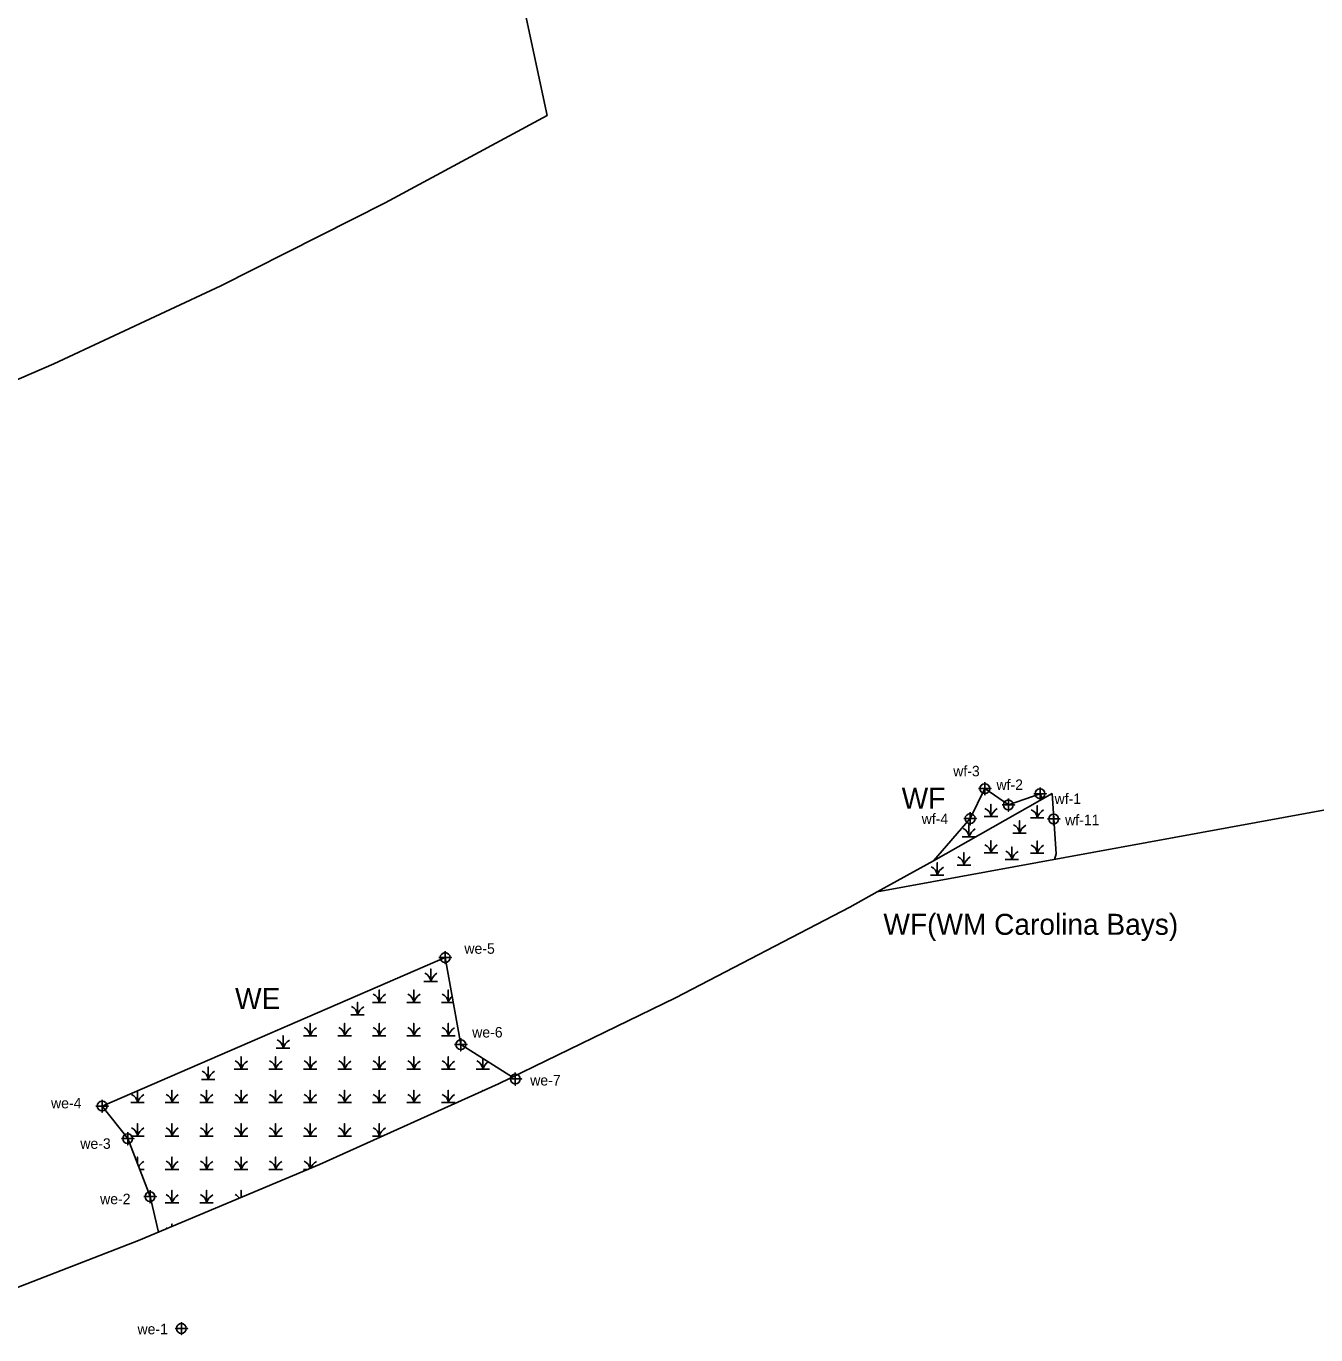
# Model space of a CAD drawing. Extents: x 2174810 to 2196950, y 76168 to 88270.
# Drawn here: x 2175379 to 2175994, y 76289 to 76913 of the extents above; entities that cross this region are included whole.
import ezdxf

# ---------------------------------------------------------------- set-up
doc = ezdxf.new("R2010")
doc.units = 0
for name, color, linetype in [('Default', 7, 'Continuous'), ('Exist Environmental Wetland Boundary', 7, 'Continuous'), ('Exist Environmental Wetland Boundary Cogo Number', 7, 'Continuous'), ('Exist Environmental Wetland Boundary Cogo Point CELL', 7, 'Continuous'), ('Exist Environmental Wetland Boundary Text', 7, 'Continuous'), ('Exist Hydro Swamp or Marsh', 7, 'Continuous')]:
    doc.layers.add(name, color=color, linetype=linetype)

msp = doc.modelspace()

# ---------------------------------------------------------------- linework, layer by layer
at = {"layer": 'Default'}
for points in [[(2175311.89, 76716.94), (2175392.42, 76751.76), (2175471.91, 76788.91), (2175550.27, 76828.38), (2175627.45, 76870.11), (2175551.73, 77223.26)], [(2176080.61, 76554.38), (2175784.69, 76500.24), (2175771.53, 76492.93), (2175688.49, 76449.77), (2175604.3, 76408.9), (2175519.02, 76370.37), (2175432.71, 76334.2), (2175345.43, 76300.42)]]:
    msp.add_lwpolyline(points, dxfattribs=at)
at = {"layer": 'Exist Environmental Wetland Boundary'}
for p, q in [((2175811.46, 76515.11), (2175868.02, 76547.06)), ((2175868.02, 76547.06), (2175869.85, 76518.43)), ((2175784.69, 76500.24), (2175811.46, 76515.11)), ((2175869.85, 76518.43), (2175869.09, 76515.68)), ((2175869.09, 76515.68), (2175869.09, 76515.68))]:
    msp.add_line(p, q, dxfattribs=at)
for points in [[(2175811.46, 76515.11), (2175828.93, 76535.2), (2175835.91, 76549.46), (2175847.11, 76541.72), (2175862.19, 76546.99), (2175863.57, 76544.43)], [(2175442.26, 76338.2), (2175438.24, 76355.14), (2175427.59, 76382.78), (2175415.44, 76398.28), (2175578.82, 76469.01), (2175586.29, 76427.53), (2175610.84, 76412.07)]]:
    msp.add_lwpolyline(points, dxfattribs=at)
at = {"layer": 'Exist Environmental Wetland Boundary Cogo Point CELL'}
for points in [[(2175835.91, 76552.46), (2175835.91, 76546.46), (2175835.91, 76549.46), (2175838.91, 76549.46), (2175832.91, 76549.46)], [(2175862.19, 76549.99), (2175862.19, 76543.99), (2175862.19, 76546.99), (2175865.19, 76546.99), (2175859.19, 76546.99)], [(2175847.11, 76544.72), (2175847.11, 76538.72), (2175847.11, 76541.72), (2175850.11, 76541.72), (2175844.11, 76541.72)], [(2175828.93, 76538.2), (2175828.93, 76532.2), (2175828.93, 76535.2), (2175831.93, 76535.2), (2175825.93, 76535.2)], [(2175868.69, 76538), (2175868.69, 76532), (2175868.69, 76535), (2175871.69, 76535), (2175865.69, 76535)], [(2175578.82, 76472.01), (2175578.82, 76466.01), (2175578.82, 76469.01), (2175581.82, 76469.01), (2175575.82, 76469.01)], [(2175586.29, 76430.53), (2175586.29, 76424.53), (2175586.29, 76427.53), (2175589.29, 76427.53), (2175583.29, 76427.53)], [(2175612.22, 76414.2), (2175612.22, 76408.2), (2175612.22, 76411.2), (2175615.22, 76411.2), (2175609.22, 76411.2)], [(2175415.44, 76401.28), (2175415.44, 76395.28), (2175415.44, 76398.28), (2175418.44, 76398.28), (2175412.44, 76398.28)], [(2175427.59, 76385.78), (2175427.59, 76379.78), (2175427.59, 76382.78), (2175430.59, 76382.78), (2175424.59, 76382.78)], [(2175438.24, 76358.14), (2175438.24, 76352.14), (2175438.24, 76355.14), (2175441.24, 76355.14), (2175435.24, 76355.14)], [(2175453.17, 76295.32), (2175453.17, 76289.32), (2175453.17, 76292.32), (2175456.17, 76292.32), (2175450.17, 76292.32)]]:
    msp.add_lwpolyline(points, dxfattribs=at)
for centre in [(2175835.91, 76549.46), (2175862.19, 76546.99), (2175847.11, 76541.72), (2175828.93, 76535.2), (2175868.69, 76535), (2175578.82, 76469.01), (2175586.29, 76427.53), (2175612.22, 76411.2), (2175415.44, 76398.28), (2175427.59, 76382.78), (2175438.24, 76355.14), (2175453.17, 76292.32)]:
    msp.add_circle(centre, 2.34, dxfattribs=at)
at = {"layer": 'Exist Hydro Swamp or Marsh'}
for p, q in [((2175433.25, 76368.07), (2175435.47, 76368.07)), ((2175511.28, 76368.07), (2175513.54, 76368.07))]:
    msp.add_line(p, q, dxfattribs=at)
for points in [[(2175835.58, 76536.13), (2175838.81, 76536.13), (2175838.81, 76542.05), (2175838.81, 76536.13), (2175842.03, 76536.13)], [(2175857.62, 76535.49), (2175860.84, 76535.49), (2175860.84, 76541.41), (2175860.84, 76535.49), (2175864.07, 76535.49)], [(2175825.13, 76526.5), (2175828.35, 76526.5), (2175828.35, 76532.42), (2175828.35, 76526.5), (2175831.58, 76526.5)], [(2175849.21, 76528.23), (2175852.44, 76528.23), (2175852.44, 76534.15), (2175852.44, 76528.23), (2175855.66, 76528.23)], [(2175835.58, 76518.8), (2175838.81, 76518.8), (2175838.81, 76524.72), (2175838.81, 76518.8), (2175842.03, 76518.8)], [(2175845.52, 76515.74), (2175848.74, 76515.74), (2175848.74, 76521.66), (2175848.74, 76515.74), (2175851.97, 76515.74)], [(2175857.62, 76518.67), (2175860.84, 76518.67), (2175860.84, 76524.59), (2175860.84, 76518.67), (2175864.07, 76518.67)], [(2175809.98, 76508.22), (2175813.2, 76508.22), (2175813.2, 76514.14), (2175813.2, 76508.22), (2175816.43, 76508.22)], [(2175822.72, 76513.06), (2175825.94, 76513.06), (2175825.94, 76518.98), (2175825.94, 76513.06), (2175829.17, 76513.06)], [(2175568.71, 76457.67), (2175571.93, 76457.67), (2175571.93, 76463.58), (2175571.93, 76457.67), (2175575.16, 76457.67)], [(2175544.18, 76447.66), (2175547.4, 76447.66), (2175547.4, 76453.58), (2175547.4, 76447.66), (2175550.63, 76447.66)], [(2175560.63, 76447.66), (2175563.86, 76447.66), (2175563.86, 76453.58), (2175563.86, 76447.66), (2175567.08, 76447.66)], [(2175577.08, 76447.66), (2175580.31, 76447.66), (2175580.31, 76453.58), (2175580.31, 76447.66), (2175582.66, 76447.66)], [(2175533.85, 76441.75), (2175537.08, 76441.75), (2175537.08, 76447.67), (2175537.08, 76441.75), (2175540.31, 76441.75)], [(2175511.28, 76431.75), (2175514.5, 76431.75), (2175514.5, 76437.66), (2175514.5, 76431.75), (2175517.73, 76431.75)], [(2175527.73, 76431.75), (2175530.95, 76431.75), (2175530.95, 76437.66), (2175530.95, 76431.75), (2175534.18, 76431.75)], [(2175544.18, 76431.75), (2175547.4, 76431.75), (2175547.4, 76437.66), (2175547.4, 76431.75), (2175550.63, 76431.75)], [(2175560.63, 76431.75), (2175563.86, 76431.75), (2175563.86, 76437.66), (2175563.86, 76431.75), (2175567.08, 76431.75)], [(2175577.08, 76431.75), (2175580.31, 76431.75), (2175580.31, 76437.66), (2175580.31, 76431.75), (2175583.53, 76431.75)], [(2175498.4, 76425.83), (2175501.62, 76425.83), (2175501.62, 76431.75), (2175501.62, 76425.83), (2175504.85, 76425.83)], [(2175478.37, 76415.83), (2175481.6, 76415.83), (2175481.6, 76421.75), (2175481.6, 76415.83), (2175484.83, 76415.83)], [(2175494.83, 76415.83), (2175498.05, 76415.83), (2175498.05, 76421.75), (2175498.05, 76415.83), (2175501.28, 76415.83)], [(2175511.28, 76415.83), (2175514.5, 76415.83), (2175514.5, 76421.75), (2175514.5, 76415.83), (2175517.73, 76415.83)], [(2175527.73, 76415.83), (2175530.95, 76415.83), (2175530.95, 76421.75), (2175530.95, 76415.83), (2175534.18, 76415.83)], [(2175544.18, 76415.83), (2175547.4, 76415.83), (2175547.4, 76421.75), (2175547.4, 76415.83), (2175550.63, 76415.83)], [(2175560.63, 76415.83), (2175563.86, 76415.83), (2175563.86, 76421.75), (2175563.86, 76415.83), (2175567.08, 76415.83)], [(2175577.08, 76415.83), (2175580.31, 76415.83), (2175580.31, 76421.75), (2175580.31, 76415.83), (2175583.53, 76415.83)], [(2175593.53, 76415.83), (2175596.76, 76415.83), (2175596.76, 76420.94)], [(2175596.76, 76420.94), (2175596.76, 76415.83), (2175599.98, 76415.83)], [(2175462.71, 76410.98), (2175465.94, 76410.98), (2175465.94, 76416.9), (2175465.94, 76410.98), (2175469.16, 76410.98)], [(2175429.02, 76399.91), (2175432.25, 76399.91), (2175432.25, 76405.55)], [(2175432.25, 76405.55), (2175432.25, 76399.91), (2175435.47, 76399.91)], [(2175445.47, 76399.91), (2175448.7, 76399.91), (2175448.7, 76405.83), (2175448.7, 76399.91), (2175451.92, 76399.91)], [(2175461.92, 76399.91), (2175465.15, 76399.91), (2175465.15, 76405.83), (2175465.15, 76399.91), (2175468.37, 76399.91)], [(2175478.37, 76399.91), (2175481.6, 76399.91), (2175481.6, 76405.83), (2175481.6, 76399.91), (2175484.83, 76399.91)], [(2175494.83, 76399.91), (2175498.05, 76399.91), (2175498.05, 76405.83), (2175498.05, 76399.91), (2175501.28, 76399.91)], [(2175511.28, 76399.91), (2175514.5, 76399.91), (2175514.5, 76405.83), (2175514.5, 76399.91), (2175517.73, 76399.91)], [(2175527.73, 76399.91), (2175530.95, 76399.91), (2175530.95, 76405.83), (2175530.95, 76399.91), (2175534.18, 76399.91)], [(2175544.18, 76399.91), (2175547.4, 76399.91), (2175547.4, 76405.83), (2175547.4, 76399.91), (2175550.63, 76399.91)], [(2175560.63, 76399.91), (2175563.86, 76399.91), (2175563.86, 76405.83), (2175563.86, 76399.91), (2175567.08, 76399.91)], [(2175577.08, 76399.91), (2175580.31, 76399.91), (2175580.31, 76405.83), (2175580.31, 76399.91), (2175583.53, 76399.91)], [(2175596.76, 76405.49), (2175596.76, 76405.83), (2175596.76, 76405.49)], [(2175429.02, 76383.99), (2175432.25, 76383.99), (2175432.25, 76389.91), (2175432.25, 76383.99), (2175435.47, 76383.99)], [(2175445.47, 76383.99), (2175448.7, 76383.99), (2175448.7, 76389.91), (2175448.7, 76383.99), (2175451.92, 76383.99)], [(2175461.92, 76383.99), (2175465.15, 76383.99), (2175465.15, 76389.91), (2175465.15, 76383.99), (2175468.37, 76383.99)], [(2175478.37, 76383.99), (2175481.6, 76383.99), (2175481.6, 76389.91), (2175481.6, 76383.99), (2175484.83, 76383.99)], [(2175494.83, 76383.99), (2175498.05, 76383.99), (2175498.05, 76389.91), (2175498.05, 76383.99), (2175501.28, 76383.99)], [(2175511.28, 76383.99), (2175514.5, 76383.99), (2175514.5, 76389.91), (2175514.5, 76383.99), (2175517.73, 76383.99)], [(2175527.73, 76383.99), (2175530.95, 76383.99), (2175530.95, 76389.91), (2175530.95, 76383.99), (2175534.18, 76383.99)], [(2175544.18, 76383.99), (2175547.4, 76383.99), (2175547.4, 76389.91), (2175547.4, 76383.99), (2175549.17, 76383.99)], [(2175432.25, 76370.69), (2175432.25, 76373.99), (2175432.25, 76370.69)], [(2175445.47, 76368.07), (2175448.7, 76368.07), (2175448.7, 76373.99), (2175448.7, 76368.07), (2175451.92, 76368.07)], [(2175461.92, 76368.07), (2175465.15, 76368.07), (2175465.15, 76373.99), (2175465.15, 76368.07), (2175468.37, 76368.07)], [(2175478.37, 76368.07), (2175481.6, 76368.07), (2175481.6, 76373.99), (2175481.6, 76368.07), (2175484.83, 76368.07)], [(2175494.83, 76368.07), (2175498.05, 76368.07), (2175498.05, 76373.99), (2175498.05, 76368.07), (2175501.28, 76368.07)], [(2175514.5, 76368.48), (2175514.5, 76373.99), (2175514.5, 76368.48)], [(2175445.47, 76352.16), (2175448.7, 76352.16), (2175448.7, 76358.07), (2175448.7, 76352.16), (2175451.92, 76352.16)], [(2175461.92, 76352.16), (2175465.15, 76352.16), (2175465.15, 76358.07), (2175465.15, 76352.16), (2175468.37, 76352.16)], [(2175481.6, 76354.69), (2175481.6, 76358.07), (2175481.6, 76354.69)], [(2175448.7, 76340.9), (2175448.7, 76342.16), (2175448.7, 76340.9)]]:
    msp.add_lwpolyline(points, dxfattribs=at)
for centre, radius, start, end in [((2175834.21, 76535.8), 4.61, 4.14034, 67.53497), ((2175845.65, 76533.86), 7.21, 122.12745, 161.62219), ((2175856.24, 76535.16), 4.61, 4.14034, 67.53497), ((2175867.69, 76533.22), 7.21, 122.12745, 161.62219), ((2175823.75, 76526.17), 4.61, 4.14034, 67.53497), ((2175835.19, 76524.23), 7.21, 122.12745, 161.62219), ((2175847.84, 76527.89), 4.61, 4.14034, 67.53497), ((2175859.28, 76525.96), 7.21, 122.12745, 161.62219), ((2175834.21, 76518.46), 4.61, 4.14034, 67.53497), ((2175845.65, 76516.52), 7.21, 122.12745, 161.62219), ((2175856.24, 76518.34), 4.61, 4.14034, 67.53497), ((2175867.69, 76516.4), 7.21, 122.12745, 161.62219), ((2175821.34, 76512.73), 4.61, 4.14034, 67.53497), ((2175832.78, 76510.79), 7.21, 122.12745, 161.62219), ((2175844.14, 76515.41), 4.61, 4.14034, 67.53497), ((2175855.58, 76513.47), 7.21, 122.12745, 161.62219), ((2175808.6, 76507.89), 4.61, 4.14034, 67.53497), ((2175820.05, 76505.95), 7.21, 122.12745, 161.62219), ((2175567.33, 76457.33), 4.61, 4.14034, 67.53497), ((2175578.77, 76455.39), 7.21, 122.12745, 161.62219), ((2175542.8, 76447.33), 4.61, 4.14034, 67.53497), ((2175554.25, 76445.39), 7.21, 122.12745, 161.62219), ((2175559.26, 76447.33), 4.61, 4.14034, 67.53497), ((2175570.7, 76445.39), 7.21, 122.12745, 161.62219), ((2175575.71, 76447.33), 4.61, 4.14034, 67.53497), ((2175532.48, 76441.42), 4.61, 4.14034, 67.53497), ((2175543.92, 76439.48), 7.21, 122.12745, 161.62219), ((2175587.15, 76445.39), 7.21, 133.9993, 161.62219), ((2175509.9, 76431.41), 4.61, 4.14034, 67.53497), ((2175521.34, 76429.47), 7.21, 122.12745, 161.62219), ((2175526.35, 76431.41), 4.61, 4.14034, 67.53497), ((2175537.79, 76429.47), 7.21, 122.12745, 161.62219), ((2175542.8, 76431.41), 4.61, 4.14034, 67.53497), ((2175554.25, 76429.47), 7.21, 122.12745, 161.62219), ((2175559.26, 76431.41), 4.61, 4.14034, 67.53497), ((2175570.7, 76429.47), 7.21, 122.12745, 161.62219), ((2175575.71, 76431.41), 4.61, 4.14034, 67.53497), ((2175587.15, 76429.47), 7.21, 122.12745, 161.62219), ((2175497.02, 76425.5), 4.61, 4.14034, 67.53497), ((2175508.46, 76423.56), 7.21, 122.12745, 161.62219), ((2175461.34, 76410.65), 4.61, 4.14034, 67.53497), ((2175472.78, 76408.71), 7.21, 122.12745, 161.62219), ((2175477, 76415.49), 4.61, 4.14034, 67.53497), ((2175488.44, 76413.56), 7.21, 122.12745, 161.62219), ((2175493.45, 76415.49), 4.61, 4.14034, 67.53497), ((2175504.89, 76413.56), 7.21, 122.12745, 161.62219), ((2175509.9, 76415.49), 4.61, 4.14034, 67.53497), ((2175521.34, 76413.56), 7.21, 122.12745, 161.62219), ((2175526.35, 76415.49), 4.61, 4.14034, 67.53497), ((2175537.79, 76413.56), 7.21, 122.12745, 161.62219), ((2175542.8, 76415.49), 4.61, 4.14034, 67.53497), ((2175554.25, 76413.56), 7.21, 122.12745, 161.62219), ((2175559.26, 76415.49), 4.61, 4.14034, 67.53497), ((2175570.7, 76413.56), 7.21, 122.12745, 161.62219), ((2175575.71, 76415.49), 4.61, 4.14034, 67.53497), ((2175587.15, 76413.56), 7.21, 122.12745, 161.62219), ((2175592.16, 76415.49), 4.61, 4.14034, 67.53497), ((2175603.6, 76413.56), 7.21, 126.64867, 161.62219), ((2175427.65, 76399.58), 4.61, 4.14034, 67.53497), ((2175439.09, 76397.64), 7.21, 122.12745, 161.62219), ((2175444.1, 76399.58), 4.61, 4.14034, 67.53497), ((2175455.54, 76397.64), 7.21, 122.12745, 161.62219), ((2175460.55, 76399.58), 4.61, 4.14034, 67.53497), ((2175471.99, 76397.64), 7.21, 122.12745, 161.62219), ((2175477, 76399.58), 4.61, 4.14034, 67.53497), ((2175488.44, 76397.64), 7.21, 122.12745, 161.62219), ((2175493.45, 76399.58), 4.61, 4.14034, 67.53497), ((2175504.89, 76397.64), 7.21, 122.12745, 161.62219), ((2175509.9, 76399.58), 4.61, 4.14034, 67.53497), ((2175521.34, 76397.64), 7.21, 122.12745, 161.62219), ((2175526.35, 76399.58), 4.61, 4.14034, 67.53497), ((2175537.79, 76397.64), 7.21, 122.12745, 161.62219), ((2175542.8, 76399.58), 4.61, 4.14034, 67.53497), ((2175554.25, 76397.64), 7.21, 122.12745, 161.62219), ((2175559.26, 76399.58), 4.61, 4.14034, 67.53497), ((2175570.7, 76397.64), 7.21, 122.12745, 161.62219), ((2175575.71, 76399.58), 4.61, 4.14034, 67.53497), ((2175587.15, 76397.64), 7.21, 122.12745, 161.62219), ((2175427.65, 76383.66), 4.61, 4.14034, 67.53497), ((2175439.09, 76381.72), 7.21, 122.12745, 161.62219), ((2175444.1, 76383.66), 4.61, 4.14034, 67.53497), ((2175455.54, 76381.72), 7.21, 122.12745, 161.62219), ((2175460.55, 76383.66), 4.61, 4.14034, 67.53497), ((2175471.99, 76381.72), 7.21, 122.12745, 161.62219), ((2175477, 76383.66), 4.61, 4.14034, 67.53497), ((2175488.44, 76381.72), 7.21, 122.12745, 161.62219), ((2175493.45, 76383.66), 4.61, 4.14034, 67.53497), ((2175504.89, 76381.72), 7.21, 122.12745, 161.62219), ((2175509.9, 76383.66), 4.61, 4.14034, 67.53497), ((2175521.34, 76381.72), 7.21, 122.12745, 161.62219), ((2175526.35, 76383.66), 4.61, 4.14034, 67.53497), ((2175537.79, 76381.72), 7.21, 122.12745, 161.62219), ((2175542.8, 76383.66), 4.61, 4.14034, 67.53497), ((2175554.25, 76381.72), 7.21, 122.12745, 161.62219), ((2175439.09, 76365.8), 7.21, 122.12745, 151.00607), ((2175444.1, 76367.74), 4.61, 4.14034, 67.53497), ((2175455.54, 76365.8), 7.21, 122.12745, 161.62219), ((2175460.55, 76367.74), 4.61, 4.14034, 67.53497), ((2175471.99, 76365.8), 7.21, 122.12745, 161.62219), ((2175477, 76367.74), 4.61, 4.14034, 67.53497), ((2175488.44, 76365.8), 7.21, 122.12745, 161.62219), ((2175493.45, 76367.74), 4.61, 4.14034, 67.53497), ((2175504.89, 76365.8), 7.21, 122.12745, 161.62219), ((2175509.9, 76367.74), 4.61, 8.95005, 67.53497), ((2175521.34, 76365.8), 7.21, 122.12745, 157.57268), ((2175444.1, 76351.82), 4.61, 4.14034, 67.53497), ((2175455.54, 76349.88), 7.21, 122.12745, 161.62219), ((2175460.55, 76351.82), 4.61, 4.14034, 67.53497), ((2175471.99, 76349.88), 7.21, 122.12745, 161.62219), ((2175477, 76351.82), 4.61, 33.54359, 67.53497), ((2175488.44, 76349.88), 7.21, 122.12745, 123.7575), ((2175444.1, 76335.91), 4.61, 60.56551, 67.53497)]:
    msp.add_arc(centre, radius, start, end, dxfattribs=at)

# ---------------------------------------------------------------- texts
at = {"layer": 'Exist Environmental Wetland Boundary Cogo Number'}
for s, p in [('wf-3', (2175820.84, 76555.31)), ('wf-2', (2175841.44, 76548.82)), ('wf-1', (2175869.12, 76542.15)), ('wf-4', (2175805.83, 76532.58)), ('wf-11', (2175874.15, 76532.05)), ('we-5', (2175587.98, 76470.79)), ('we-6', (2175591.7, 76430.92)), ('we-7', (2175619.34, 76408.06)), ('we-4', (2175391.08, 76397.16)), ('we-3', (2175405.03, 76377.89)), ('we-2', (2175414.45, 76351.53)), ('we-1', (2175432.26, 76289.57))]:
    msp.add_text(s, height=5, dxfattribs=at).set_placement(p)
at = {"layer": 'Exist Environmental Wetland Boundary Text'}
for s, p in [('WF', (2175796.3, 76539.89)), ('WF(WM Carolina Bays)', (2175787.6, 76479.83)), ('WE', (2175478.76, 76444.44))]:
    msp.add_text(s, height=10, dxfattribs=at).set_placement(p)

doc.saveas('drawing.dxf')
